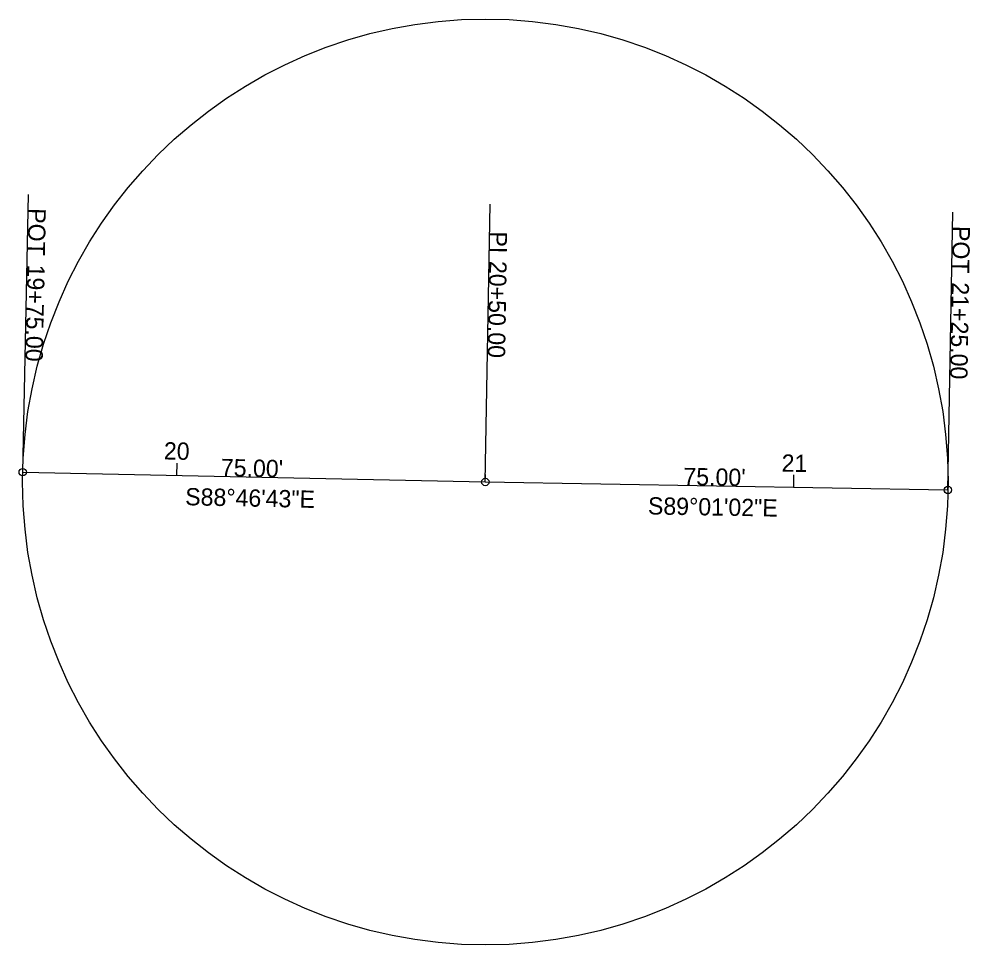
# Model space of a CAD drawing. Extents: x 1652407 to 1652790, y 606471 to 608012.
# Drawn here: x 1652477 to 1652631.1, y 607190.1 to 607340.1 of the extents above; entities that cross this region are included whole.
import ezdxf

# ---------------------------------------------------------------- set-up
doc = ezdxf.new("R2010")
doc.units = 0
for name, color, linetype in [('Default', 7, 'Continuous'), ('RW_X_CL', 7, 'Continuous'), ('SV_X_Random_Point', 7, 'Continuous'), ('SV_X_Shot_Marker', 7, 'Continuous'), ('UT_X_Water_Cells', 7, 'Continuous'), ('VG_X_Cells', 7, 'Continuous')]:
    doc.layers.add(name, color=color, linetype=linetype)

msp = doc.modelspace()

# ---------------------------------------------------------------- linework, layer by layer
at = {"layer": 'Default'}
msp.add_circle((1652552.56, 607265.15), 75, dxfattribs=at)
at = {"layer": 'RW_X_CL'}
for p, q in [((1652477.57, 607266.75), (1652552.56, 607265.15)), ((1652552.56, 607265.15), (1652627.54, 607263.86))]:
    msp.add_line(p, q, dxfattribs=at)
at = {"layer": 'SV_X_Random_Point'}
for p, q in [((1652477.57, 607266.75), (1652478.53, 607311.74)), ((1652552.56, 607265.15), (1652553.33, 607310.14)), ((1652627.54, 607263.86), (1652628.32, 607308.86))]:
    msp.add_line(p, q, dxfattribs=at)
for centre in [(1652477.57, 607266.75), (1652552.56, 607265.15), (1652627.54, 607263.86)]:
    msp.add_circle(centre, 0.6, dxfattribs=at)
at = {"layer": 'UT_X_Water_Cells'}
for p, q in [((1652502.57, 607266.22), (1652502.61, 607268.21)), ((1652552.56, 607265.15), (1652552.58, 607266.35)), ((1652602.55, 607264.29), (1652602.58, 607266.29))]:
    msp.add_line(p, q, dxfattribs=at)

# ---------------------------------------------------------------- texts
at = {"layer": 'SV_X_Random_Point'}
for s, rotation, p in [('POT', 268.7786, (1652478.53, 607309.53)), ('POT', 269.0172, (1652628.33, 607306.65)), ('PI', 269.0172, (1652553.3, 607305.76)), ('19+75.00', 268.7786, (1652478.34, 607300.4)), ('20+50.00', 269.0172, (1652553.22, 607300.98)), ('21+25.00', 269.0172, (1652628.17, 607297.52))]:
    msp.add_text(s, height=2.8, rotation=rotation, dxfattribs=at).set_placement(p)
at = {"layer": 'SV_X_Shot_Marker'}
for s, rotation, p in [('S88°46\'43"E', 358.7786, (1652503.89, 607261.39)), ('S89°01\'02"E', 359.0172, (1652578.9, 607259.9))]:
    msp.add_text(s, height=2.8, rotation=rotation, dxfattribs=at).set_placement(p)
at = {"layer": 'UT_X_Water_Cells'}
for s, rotation, p in [('20', 358.7786, (1652500.43, 607268.81)), ('21', 359.0172, (1652600.57, 607266.83))]:
    msp.add_text(s, height=2.8, rotation=rotation, dxfattribs=at).set_placement(p)
at = {"layer": 'VG_X_Cells'}
for rotation, p in [(358.7786, (1652509.67, 607266.11)), (359.0172, (1652584.65, 607264.65))]:
    msp.add_text("75.00'", height=2.8, rotation=rotation, dxfattribs=at).set_placement(p)

doc.saveas('drawing.dxf')
